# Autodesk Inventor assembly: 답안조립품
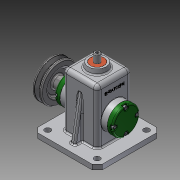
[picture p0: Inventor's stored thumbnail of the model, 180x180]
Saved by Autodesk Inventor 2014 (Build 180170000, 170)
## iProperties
Created: 2016-02
Part Number: 답안조립품
Document SubType Name: Assembly
Designer: Administrator
Author: Administrator
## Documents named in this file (16)
- C:\Users\Administrator\Desktop\460211V1032\답안조립품.iam
- C:\Users\Administrator\Desktop\460211V1032\1-본체.ipt
- C:\Users\Administrator\Desktop\460211V1032\편심축.ipt
- C:\Users\Administrator\Desktop\460211V1032\뒤커버.ipt
- C:\Users\Administrator\Desktop\460211V1032\베어링 12 x 32 x 10.ipt
- C:\Users\Administrator\Desktop\460211V1032\링크.ipt
- C:\Users\Administrator\Desktop\460211V1032\슬라이드.ipt
- C:\Users\Administrator\Desktop\460211V1032\고정핀 1.2 x 10.ipt
- C:\Users\Administrator\Desktop\460211V1032\핀 5 x 18.ipt
- C:\Users\Administrator\Desktop\460211V1032\부시.ipt
- C:\Users\Administrator\Desktop\460211V1032\앞커버.ipt
- C:\Users\Administrator\Desktop\460211V1032\오일실 12 25 7.ipt
- C:\Users\Administrator\Desktop\460211V1032\볼트 M4 x 12.ipt
- C:\Users\Administrator\Desktop\460211V1032\키 4 x 4 x 10.ipt
- C:\Users\Administrator\Desktop\460211V1032\멈춤나사 M3x8.ipt
- C:\Users\Administrator\Desktop\460211V1032\V벨트풀리.ipt
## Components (12 placed, 5 different names)
1. 1-본체:1 — 각도:2, 각도:3
2. 고정핀 1.2 x 10:1 — 각도:4
3. 핀 5 x 18:1 — 각도:4
4. V벨트풀리:1
5. ISO 4762 M4 x 12:1 — 각도:2
6. ISO 4762 M4 x 12:3
7. ISO 4762 M4 x 12:4
8. ISO 4762 M4 x 12:5
9. ISO 4762 M4 x 12:2 — 각도:3
10. ISO 4762 M4 x 12:6
11. ISO 4762 M4 x 12:7
12. ISO 4762 M4 x 12:8
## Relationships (3: Angle 3)
- 각도:2 [Angle]: 1-본체:1 ↔ ISO 4762 M4 x 12:1
- 각도:3 [Angle]: 1-본체:1 ↔ ISO 4762 M4 x 12:2
- 각도:4 [Angle]: 고정핀 1.2 x 10:1 ↔ 핀 5 x 18:1
